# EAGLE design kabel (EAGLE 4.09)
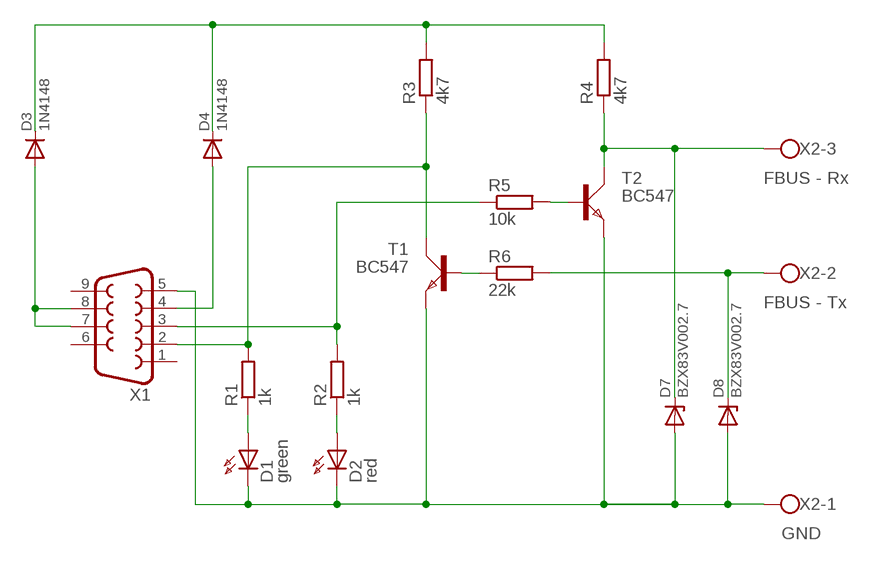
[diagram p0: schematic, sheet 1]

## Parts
D1  green  LED3MM  [LED3MM]
D2  red  LED3MM  [LED3MM]
D3  1N4148  [DO35-10]
D4  1N4148  [DO35-10]
D7  BZX83V002.7  BZX85  [DO41Z10]
D8  BZX83V002.7  BZX85  [DO41Z10]
R1  1k  R-EU_0207/7  [0207/7]
R2  1k  R-EU_0207/7  [0207/7]
R3  4k7  R-EU_0207/7  [0207/7]
R4  4k7  R-EU_0207/7  [0207/7]
R5  10k  R-EU_0207/7  [0207/7]
R6  22k  R-EU_0207/7  [0207/7]
T1  BC547  [SOT54A]
T2  BC547  [SOT54A]
X1  F09HP  [F09HP]
X2  AK500/3  [AK500/3]

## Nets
N$1: R1.2 R3.1 T1.C X1.2
N$2: D3.A X1.7 X1.8
N$3: D1.K(C) D2.K(C) D7.A D8.A T1.E T2.E X1.5 X2.1
N$4: D4.A X1.4
N$5: D2.A R2.1
N$6: D3.K D4.K R3.2 R4.2
N$7: R6.1 T1.B
N$8: D8.K R6.2 X2.2
N$9: R5.2 T2.B
N$10: D1.A R1.1
N$11: D7.K R4.1 T2.C X2.3
N$15: R2.2 R5.1 X1.3
Unconnected: X1.1 X1.6 X1.9

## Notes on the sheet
- FBUS - Rx
- FBUS - Tx
- GND

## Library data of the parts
D1 D2 = led:LED: LED
D3 D4 = diode:1N4148
D7 D8 = diode:BZX85
R1-R6 = rcl:R-EU_: RESISTOR, European symbol
T1 T2 = trans-sm:BC547
X1 = con-subd:F09: SUB-D
X2 = con-ptr500-upr:AK500/3: CONNECTOR

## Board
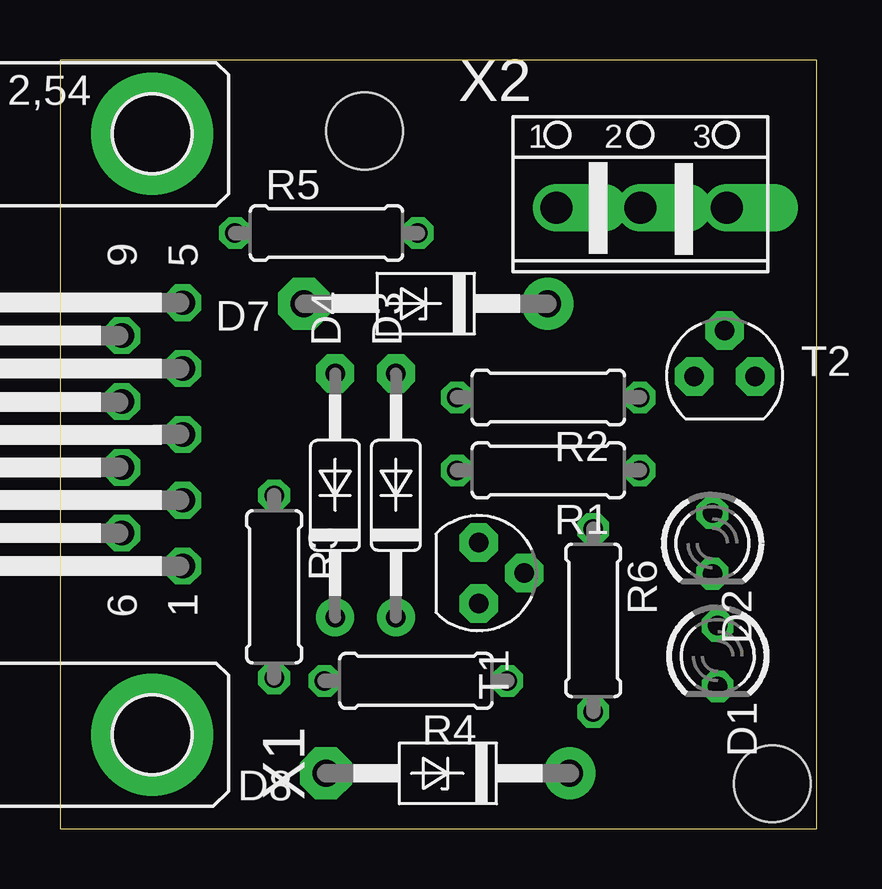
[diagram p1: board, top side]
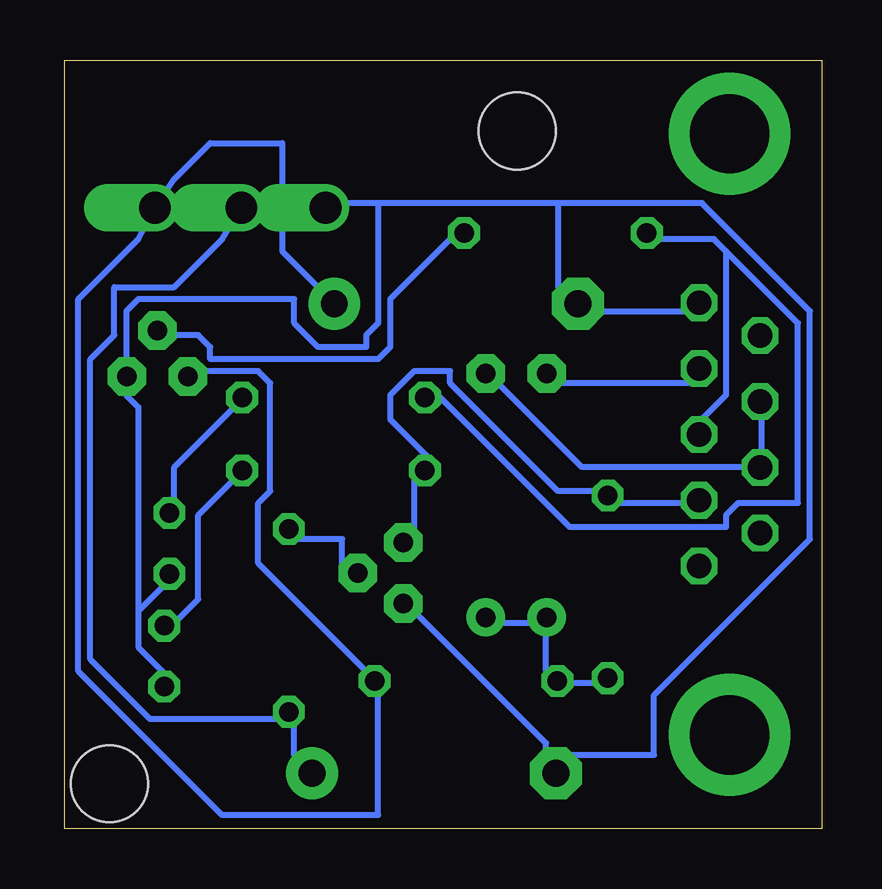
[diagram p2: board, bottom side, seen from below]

Size 31.56 x 32.03 mm. Coordinates in mm from the lower left corner, seen from the top.
Outline: 0,0 31.56,0 31.56,32.03 0,32.03 0,0
Copper layers used: Bottom
Holes 3.2 mm at 12.7,29.07 29.7,1.87

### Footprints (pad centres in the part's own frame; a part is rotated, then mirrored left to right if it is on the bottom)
LED3MM = drill 0.813 octagon: A -1.27,0; K 1.27,0
DO35-10 = drill 0.813 pad 1.6 octagon: A 5.08,0 | drill 0.813 pad 1.6 round: K -5.08,0
DO41Z10 = drill 1.118 pad 2.159 octagon: A 5.08,0 | drill 1.118 pad 2.159 round: K -5.08,0
0207/7 = drill 0.813 octagon: 1 -3.81,0; 2 3.81,0
SOT54A = drill 0.813 pad 1.6 octagon: B 0,1.905; C -1.27,0; E 1.27,0
F09HP = drill 1.016 octagon: 1 -5.486,-1.27; 2 -2.743,-1.27; 3 0,-1.27; 4 2.743,-1.27; 5 5.486,-1.27; 6 -4.115,1.27; 7 -1.372,1.27; 8 1.372,1.27; 9 4.115,1.27 | drill 3.302 pad 5.08 round: G1 -12.522,0; G2 12.522,0
AK500/3 = drill 1.321 offset: 1 -3.504,0; 2 0,0; 3 3.604,0

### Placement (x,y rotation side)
D1  27.42,7.19 270 top
D2  27.2,11.89 270 top
D3  14.01,13.89 90 top
D4  11.47,13.89 90 top
D7  15.25,21.88 180 top
D8  16.17,2.31 180 top
R1  20.36,14.93 180 top
R2  20.36,17.97 180 top
R3  8.93,10.08 270 top
R4  14.84,6.16 180 top
R5  11.11,24.82 0 top
R6  22.23,8.68 270 top
T1  17.45,10.65 270 top
T2  27.71,18.85 0 top
X1  3.85,16.43 90 top
X2  24.2,25.87 0 top

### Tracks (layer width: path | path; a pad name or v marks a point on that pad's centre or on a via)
N$1
  Bottom 0.254: T1.C 17,12.57 17,14.57 R1.2 16.5,15.57 18,17.07 18,18.07 17,19.07 15.5,19.07 15.5,18.57 11,14.07 9.5,14.07 R3.1 8.5,13.57 5.5,13.57 X1.2
N$2
  Bottom 0.254: X1.8 2.5,17.07 2.5,15.57 X1.7 3,15.07 10,15.07 13.5,18.57 D3.A
N$3
  Bottom 0.254: 28.5,9.07 28.5,7.57 27.5,6.57 D1.K | 28.5,9.07 27.5,10.07 D2.K | 28.5,9.07 28.5,17.57 29,18.07 T2.E 29,19.57 29,21.57 28.5,22.07 22,22.07 22,21.07 21,20.07 19,20.07 19,20.57 18.5,21.07 18.5,26.07 | T1.E 17,9.07 11.5,3.57 11.5,3.07 D8.A 10.5,3.07 7,3.07 7,5.57 0.5,12.07 0.5,21.57 5,26.07 11,26.07 | X1.5 5.5,21.57 9.5,21.57 D7.A 11,22.57 11,26.07 | 11,26.07 18.5,26.07 | 18.5,26.07 20,26.07 X2.1
N$4
  Bottom 0.254: X1.4 5.5,18.57 11,18.57 D4.A
N$5
  Bottom 0.254: R2.1 24.5,17.57 27,15.07 27,13.57 D2.A
N$6
  Bottom 0.254: R3.2 9.5,6.07 10.5,6.07 R4.2 11.5,6.57 11.5,8.07 D4.K 12,8.57 13.5,8.57 D3.K
N$7
  Bottom 0.254: R6.1 22,12.07 20,12.07 20,11.07 T1.B
N$8
  Bottom 0.254: D8.K 22,3.07 22,4.57 R6.2 22.5,4.57 28,4.57 30.5,7.07 30.5,19.57 29.5,20.57 29.5,22.57 27,22.57 25,24.57 X2.2
N$9
  Bottom 0.254: R5.2 15.5,24.57 18,22.07 18,20.07 18.5,19.57 25.5,19.57 25.5,20.07 26,20.57 27,20.57 T2.B
N$10
  Bottom 0.254: R1.1 24.5,14.57 26,13.07 26,9.57 27,8.57 D1.A
N$11
  Bottom 0.254: D7.K 21,22.57 22.5,24.07 22.5,28.57 25.5,28.57 27,27.07 X2.3 28.5,24.57 31,22.07 31,6.57 25,0.57 18.5,0.57 18.5,5.57 R4.1 19,6.57 23.5,11.07 23.5,13.57 23,14.07 23,18.57 23.5,19.07 26,19.07 T2.C
N$15
  Bottom 0.254: 4,24.07 4.5,24.57 7,24.57 R5.1 | 4,24.07 1,21.07 1,13.57 3.5,13.57 4,13.07 4,12.57 10.5,12.57 16,18.07 R2.2 | 4,24.07 4,18.07 5,17.07 X1.3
